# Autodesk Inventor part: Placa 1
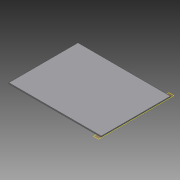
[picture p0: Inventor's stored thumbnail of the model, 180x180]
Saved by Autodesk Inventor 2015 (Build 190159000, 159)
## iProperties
Created: 2015-04
Part Number: Placa 1
Material: Generic
Document SubType Name: Modeling
Designer: suporte
Density: 1 g/cm^3
Appearance: Default
Author: suporte
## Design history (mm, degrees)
workplane "Work Plane1"
sketch "Sketch1"
  geometry: L1 (50, -381.638)-(50, 1443.362) reference; L2 (50, 706.099)-(-2050, 706.099); L3 (-2050, 706.099)-(-2050, 618.599); L4 (-2050, 618.599)-(50, 618.599); L5 (50, -41.401)-(50, 706.099); L6 (-2050, 706.099)-(50, 706.099) reference; L7 (-2050, 618.599)-(50, 618.599) reference; 1 further point
  constraints: 8 end point, 3 point on line, 2 perpendicular, 1 horizontal
extrude "Extrusion1" new body sketch "Sketch1" distance "d0" = 12.5; taper "d1" = 0 deg
body "Solid1"
node "Reference1"
node "Reference2"
node "Reference3"
node "Reference4"
